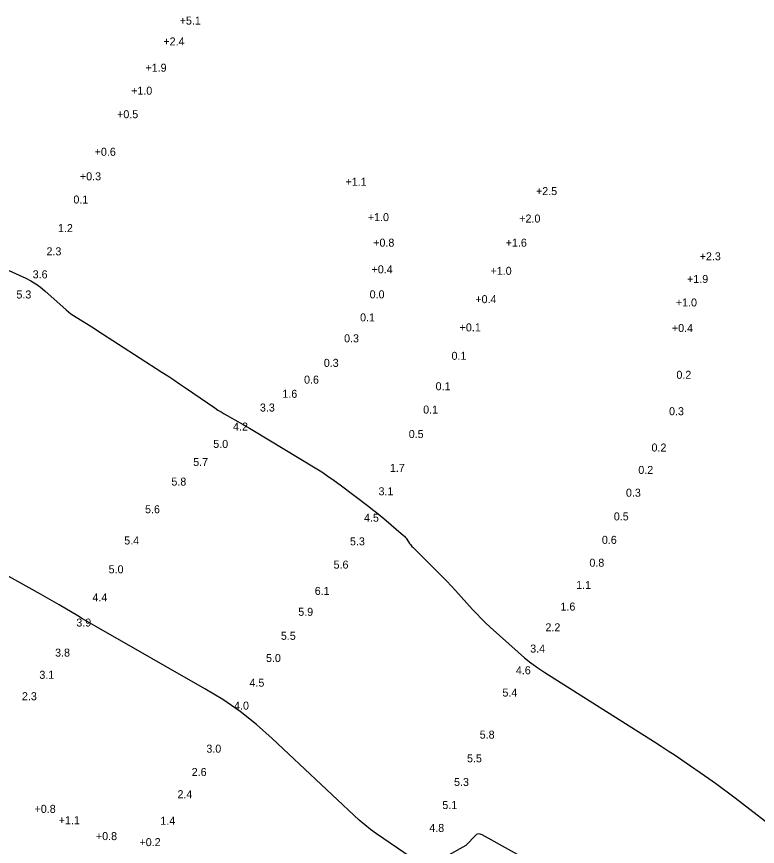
# Model space of a CAD drawing. Extents: x 837127 to 848654, y 3074248 to 3079868.
# Drawn here: x 844231.4 to 844520.6, y 3079266 to 3079590 of the extents above; entities that cross this region are included whole.
import ezdxf

# ---------------------------------------------------------------- set-up
doc = ezdxf.new("R2010")
doc.units = 0
doc.layers.add('V-HYDS-MAJR', color=7, linetype='Continuous')
doc.layers.add('V-HYDS-SOUN', color=7, linetype='Continuous')

msp = doc.modelspace()

# ---------------------------------------------------------------- linework, layer by layer
at = {"layer": 'V-HYDS-MAJR'}
for points in [[(844187.79, 3079509.13), (844234.95, 3079487.84), (844236.96, 3079486.84), (844238.88, 3079485.69), (844240.7, 3079484.39), (844242.42, 3079482.95), (844250.71, 3079475.48), (844251.62, 3079474.7), (844252.56, 3079473.96), (844253.54, 3079473.27), (844254.55, 3079472.63), (844258.65, 3079470.15), (844259.67, 3079469.53), (844260.69, 3079468.9), (844261.71, 3079468.26), (844262.72, 3079467.61), (844288.03, 3079451.23), (844290.37, 3079449.71), (844292.69, 3079448.17), (844295.01, 3079446.62), (844297.32, 3079445.05), (844308.77, 3079437.21), (844309.95, 3079436.42), (844311.16, 3079435.65), (844312.38, 3079434.91), (844313.62, 3079434.21), (844318.62, 3079431.43), (844319.87, 3079430.73), (844321.11, 3079430.02), (844322.34, 3079429.29), (844323.57, 3079428.56), (844347.95, 3079413.79), (844350.46, 3079412.22), (844352.92, 3079410.6), (844355.34, 3079408.91), (844357.72, 3079407.17), (844368.89, 3079398.73), (844370.36, 3079397.6), (844371.82, 3079396.44), (844373.26, 3079395.27), (844374.68, 3079394.07), (844382.41, 3079387.46), (844382.78, 3079387.13), (844383.11, 3079386.77), (844383.43, 3079386.39), (844383.71, 3079385.99), (844384.8, 3079384.33), (844385.08, 3079383.92), (844385.38, 3079383.53), (844385.7, 3079383.16), (844386.04, 3079382.8), (844395.93, 3079373.03), (844397.67, 3079371.29), (844399.38, 3079369.52), (844401.06, 3079367.73), (844402.72, 3079365.91), (844409.3, 3079358.58), (844410.97, 3079356.78), (844412.68, 3079355.02), (844414.44, 3079353.3), (844416.25, 3079351.63), (844427.15, 3079341.83), (844429.62, 3079339.7), (844432.17, 3079337.68), (844434.81, 3079335.77), (844437.53, 3079333.97), (844480.37, 3079306.83), (844483.06, 3079305.11), (844485.74, 3079303.36), (844488.4, 3079301.58), (844491.04, 3079299.77), (844501.56, 3079292.5), (844504.18, 3079290.67), (844506.78, 3079288.8), (844509.34, 3079286.89), (844511.88, 3079284.96), (844530.7, 3079270.4)], [(844385.46, 3079261.71), (844371.9, 3079270.96), (844369.56, 3079272.63), (844367.29, 3079274.38), (844365.1, 3079276.22), (844362.97, 3079278.15), (844331.18, 3079308.12), (844325.04, 3079313.58), (844318.61, 3079318.64), (844311.89, 3079323.32), (844304.87, 3079327.59), (844262.54, 3079351.73), (844260.71, 3079352.78), (844258.88, 3079353.84), (844257.06, 3079354.91), (844255.25, 3079355.99), (844248, 3079360.31), (844246.18, 3079361.38), (844244.36, 3079362.44), (844242.52, 3079363.49), (844240.68, 3079364.52), (844175.06, 3079401.09)], [(844496.49, 3079224.13), (844413.05, 3079270.56), (844412.31, 3079270.85), (844411.6, 3079270.88), (844410.94, 3079270.64), (844410.32, 3079270.14), (844407.01, 3079266.64), (844406.85, 3079266.51), (844406.68, 3079266.43), (844400.02, 3079262.59)]]:
    msp.add_lwpolyline(points, dxfattribs=at)

# ---------------------------------------------------------------- texts
at = {"layer": 'V-HYDS-SOUN'}
for s, p in [('+5.1 ', (844295.02, 3079586.91)), ('+2.4 ', (844288.65, 3079578.77)), ('+1.9 ', (844281.66, 3079568.51)), ('+1.0 ', (844276.07, 3079559.54)), ('+0.5 ', (844270.59, 3079550.36)), ('+0.6 ', (844261.83, 3079535.69)), ('+0.3 ', (844256.09, 3079526.11)), ('+1.1 ', (844359.76, 3079523.98)), ('+2.5 ', (844434.13, 3079520.34)), ('0.1', (844253.54, 3079517.05)), ('+1.0 ', (844368.48, 3079510.17)), ('+2.0 ', (844427.6, 3079509.62)), ('1.2', (844247.5, 3079505.89)), ('+0.8 ', (844370.58, 3079500.21)), ('+1.6 ', (844422.3, 3079500.19)), ('2.3', (844243.03, 3079496.82)), ('+2.3 ', (844498.03, 3079494.86)), ('+0.4 ', (844369.94, 3079489.79)), ('3.6', (844237.63, 3079487.83)), ('+1.0 ', (844416.38, 3079489.2)), ('+1.9 ', (844493.11, 3079486.02)), ('5.3', (844231.29, 3079479.96)), (' 0.0', (844368.03, 3079480.02)), ('+0.4 ', (844410.45, 3079478.14)), ('+1.0 ', (844488.73, 3079476.84)), ('0.1', (844365.45, 3079471.02)), ('+0.1 ', (844404.32, 3079467.11)), ('+0.4 ', (844487.19, 3079466.88)), ('0.3', (844359.21, 3079462.85)), ('0.1', (844401.16, 3079456.01)), ('0.3', (844351.29, 3079453.26)), ('0.2', (844488.96, 3079448.61)), ('0.6', (844343.58, 3079446.71)), ('1.6', (844335.11, 3079441.18)), ('0.1', (844394.94, 3079444.13)), ('3.3', (844326.35, 3079435.82)), ('0.1', (844390.09, 3079435.01)), ('0.3', (844486.08, 3079434.39)), ('4.2', (844315.87, 3079428.39)), ('0.5', (844384.45, 3079425.48)), ('5.0', (844308.13, 3079421.62)), ('0.2', (844479.23, 3079420.2)), ('5.7', (844300.29, 3079414.55)), ('1.7', (844377.09, 3079412.24)), ('0.2', (844474.08, 3079411.46)), ('5.8', (844291.79, 3079406.9)), ('3.1', (844372.66, 3079403.12)), ('0.3', (844469.25, 3079402.56)), ('5.6', (844281.51, 3079396.1)), ('4.5', (844367, 3079392.8)), ('0.5', (844464.51, 3079393.31)), ('5.4', (844273.38, 3079383.91)), ('5.3', (844361.51, 3079383.57)), ('0.6', (844459.85, 3079384.15)), ('5.6', (844355.11, 3079374.48)), ('0.8', (844454.98, 3079375.22)), ('5.0', (844267.29, 3079372.66)), ('1.1', (844449.81, 3079366.53)), ('6.1', (844347.74, 3079364.22)), ('4.4', (844260.96, 3079361.68)), ('1.6', (844443.68, 3079358.1)), ('5.9', (844341.31, 3079356.06)), ('3.9', (844254.68, 3079351.86)), ('2.2', (844437.82, 3079350)), ('5.5', (844334.53, 3079346.68)), ('3.4', (844431.88, 3079341.7)), ('3.8', (844246.39, 3079340.12)), ('5.0', (844328.73, 3079338.03)), ('3.1', (844240.25, 3079331.46)), ('4.6', (844426.28, 3079333.23)), ('4.5', (844322.28, 3079328.37)), ('5.4', (844421.03, 3079324.52)), ('2.3', (844233.45, 3079323.1)), ('4.0', (844316.26, 3079319.43)), ('5.8', (844412.16, 3079308.1)), ('3.0', (844305.45, 3079302.62)), ('5.5', (844407.2, 3079298.85)), ('2.6', (844299.71, 3079293.5)), ('5.3', (844402.14, 3079289.61)), ('2.4', (844294.17, 3079284.83)), ('+0.8 ', (844238.37, 3079279.11)), ('5.1', (844397.56, 3079280.6)), ('+1.1 ', (844247.79, 3079274.69)), ('1.4', (844287.47, 3079274.47)), ('4.8', (844392.47, 3079271.67)), ('+0.8 ', (844262.32, 3079268.47)), ('+0.2 ', (844279.33, 3079266.11))]:
    msp.add_text(s, height=3.125, dxfattribs=at).set_placement(p)

doc.saveas('drawing.dxf')
